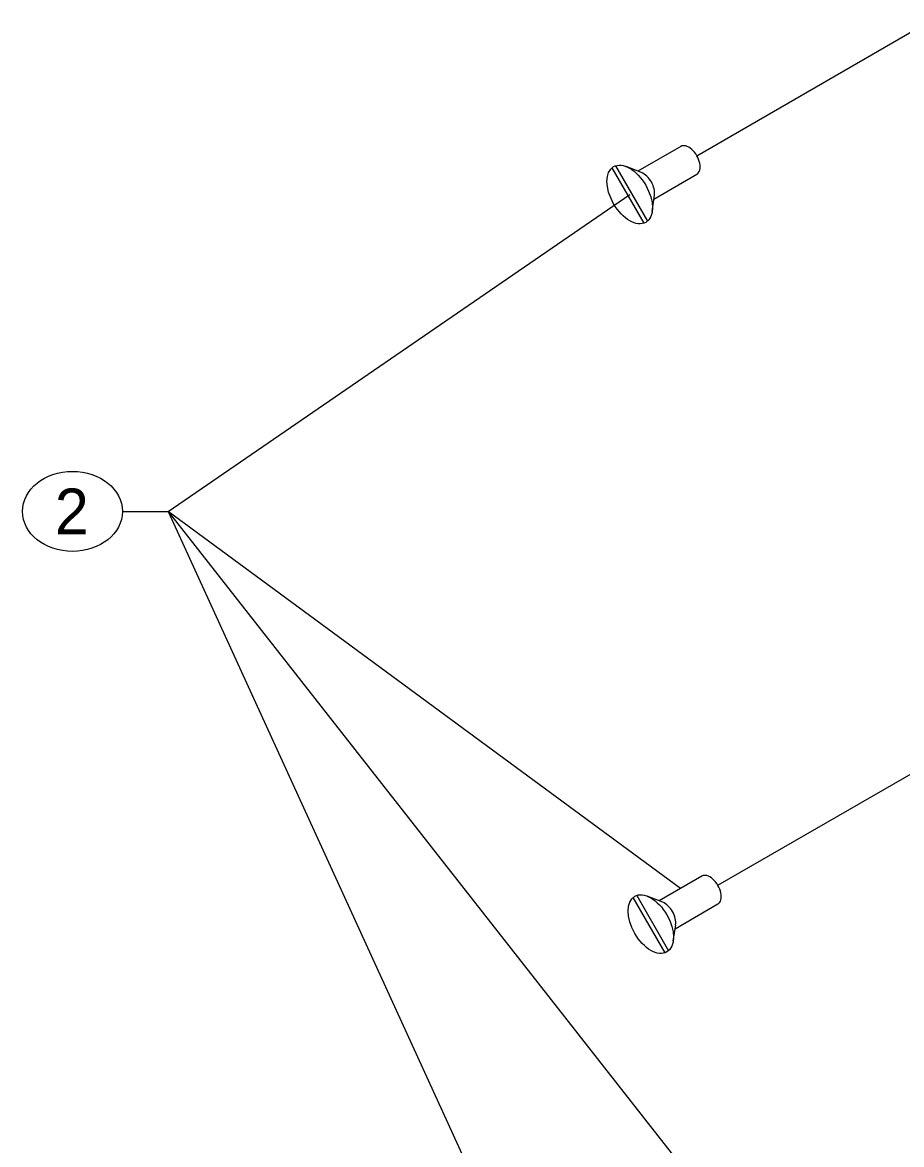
# Model space of a CAD drawing. Extents: x 99862 to 103151, y 100000 to 105076.
# Drawn here: x 100319.9 to 100627.5, y 100415.7 to 100808.2 of the extents above; entities that cross this region are included whole.
import ezdxf

# ---------------------------------------------------------------- set-up
doc = ezdxf.new("R2010")
doc.units = 0
for name, color, linetype in [('Level 15', 7, 'Continuous'), ('Level 16', 7, 'Continuous'), ('Level 20', 7, 'Continuous'), ('Level 41', 7, 'Continuous')]:
    doc.layers.add(name, color=color, linetype=linetype)

msp = doc.modelspace()

# ---------------------------------------------------------------- linework, layer by layer
at = {"layer": 'Level 15'}
for p, q in [((100370.94, 100637.15), (100532.37, 100747.98)), ((100354.94, 100637.15), (100370.94, 100637.15)), ((100550.13, 100505.31), (100370.94, 100637.15)), ((100370.94, 100637.15), (100542.74, 100261.48)), ((100370.94, 100637.15), (100767.41, 100131.77))]:
    msp.add_line(p, q, dxfattribs=at)
at = {"layer": 'Level 16'}
for p, q in [((100555.87, 100761.55), (100698.66, 100843.99)), ((100563.26, 100506.39), (100923.02, 100714.09))]:
    msp.add_line(p, q, dxfattribs=at)
at = {"layer": 'Level 20'}
msp.add_ellipse((100337.44, 100637.15), major_axis=(-17.5, 0), ratio=0.8, dxfattribs=at)
at = {"layer": 'Level 41'}
for p, q in [((100550.24, 100764.79), (100535.25, 100756.14)), ((100526.13, 100757.28), (100537.31, 100737.93)), ((100527.43, 100758.03), (100538.61, 100738.68)), ((100536.53, 100755.63), (100531.14, 100757.77)), ((100540.87, 100746.39), (100555.87, 100755.05)), ((100540.23, 100742.02), (100541.07, 100747.76)), ((100557.63, 100509.63), (100542.64, 100500.98)), ((100533.52, 100502.12), (100544.7, 100482.77)), ((100534.82, 100502.87), (100546, 100483.52)), ((100543.92, 100500.47), (100538.53, 100502.61)), ((100548.26, 100491.23), (100563.26, 100499.89)), ((100547.62, 100486.86), (100548.46, 100492.6))]:
    msp.add_line(p, q, dxfattribs=at)
for centre, start_param, end_param in [((100553.05, 100759.92), 6.28318, 9.424778), ((100553.05, 100759.92), 3.141593, 3.141605), ((100537.14, 100750.74), 0.630137, 2.511455), ((100560.44, 100504.76), 6.28318, 9.424778), ((100560.44, 100504.76), 3.141593, 3.141605), ((100544.53, 100495.58), 0.630137, 2.511455)]:
    msp.add_ellipse(centre, major_axis=(2.81, -4.87), ratio=0.57735, start_param=start_param, end_param=end_param, dxfattribs=at)
for centre in [(100532.37, 100747.98), (100539.76, 100492.82)]:
    msp.add_ellipse(centre, major_axis=(-5.63, 9.74), ratio=0.57735, dxfattribs=at)

# ---------------------------------------------------------------- texts
at = {"layer": 'Level 20'}
msp.add_text('2', height=16, dxfattribs=at).set_placement((100331.26, 100629.15))

doc.saveas('drawing.dxf')
